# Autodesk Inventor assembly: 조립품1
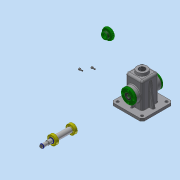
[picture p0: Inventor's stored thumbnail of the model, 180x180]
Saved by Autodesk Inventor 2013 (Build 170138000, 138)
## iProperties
Created: 2018-10
Part Number: 조립품1
Document SubType Name: Assembly
Designer: Administrator
Author: Administrator
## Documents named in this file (14)
- C:\Users\Administrator\Desktop\481013V1008\조립품1.iam
- C:\Users\Administrator\Desktop\481013V1008\1.본체.ipt
- C:\Users\Administrator\Desktop\481013V1008\V-벨트풀리.ipt
- C:\Users\Administrator\Desktop\481013V1008\뒤커버.ipt
- C:\Users\Administrator\Desktop\481013V1008\멈춤링 15 x 1.ipt
- C:\Users\Administrator\Desktop\481013V1008\베어링 15 x 35 x 11.ipt
- C:\Users\Administrator\Desktop\481013V1008\볼트 M4 x 10.ipt
- C:\Users\Administrator\Desktop\481013V1008\볼트 M6 x 12.ipt
- C:\Users\Administrator\Desktop\481013V1008\상부캡.ipt
- C:\Users\Administrator\Desktop\481013V1008\앞커버.ipt
- C:\Users\Administrator\Desktop\481013V1008\오일실 15 25 7.ipt
- C:\Users\Administrator\Desktop\481013V1008\와셔.ipt
- C:\Users\Administrator\Desktop\481013V1008\축.ipt
- C:\Users\Administrator\Desktop\481013V1008\키 5 x 5 x 14.ipt
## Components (2 placed, 2 different names)
1. 1.본체:1
2. V-벨트풀리:1
